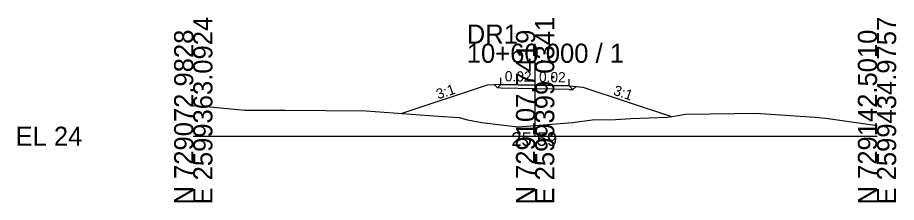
# Model space of a CAD drawing. Extents: x -26 to 1162, y -10 to 9515.
# Drawn here: x -25.7 to 102.8, y 2990.3 to 3017.4 of the extents above; entities that cross this region are included whole.
import ezdxf

# ---------------------------------------------------------------- set-up
doc = ezdxf.new("R2010")
doc.units = 0
for name, color, linetype in [('Exist Cross Section Cell', 7, 'Continuous'), ('Exist XS Center Line Elevation Label', 7, 'Continuous'), ('Exist XS Ground Line', 7, 'Continuous'), ('Prop XS Ditch Slope Text', 7, 'Continuous'), ('Prop XS Dump Level', 7, 'Continuous'), ('Prop XS EOT Tick Mark', 7, 'Continuous'), ('Prop XS Finish Grade', 7, 'Continuous'), ('Prop XS Finish Grade Earthwork', 7, 'Continuous'), ('Prop XS Finish Grade Pavement', 7, 'Continuous'), ('Prop XS Pvmt Edge Slope', 7, 'Continuous'), ('Prop XS SE Text', 7, 'Continuous'), ('Prop XS Subgrade Earthwork', 7, 'Continuous')]:
    doc.layers.add(name, color=color, linetype=linetype)

msp = doc.modelspace()

# ---------------------------------------------------------------- linework, layer by layer
at = {"layer": 'Exist Cross Section Cell'}
for p, q in [((50, 3000), (50, 3013.55)), ((0, 3000), (50, 3000)), ((50, 3000), (100, 3000))]:
    msp.add_line(p, q, dxfattribs=at)
at = {"layer": 'Exist XS Ground Line'}
msp.add_lwpolyline([(0, 3004.52), (0.89, 3004.45), (7.54, 3003.8), (13.39, 3003.84), (25.31, 3003.72), (35.83, 3002.93), (38.89, 3002.76), (40.1, 3002.4), (42.2, 3002.02), (44.6, 3001.74), (47.45, 3001.39), (50, 3001.59), (55.45, 3002), (58.36, 3002.42), (61.73, 3002.45), (64, 3002.59), (69.36, 3002.79), (70.62, 3003.01), (72.01, 3003.21), (79.15, 3003.35), (82.23, 3003.4), (90.94, 3002.77), (92.53, 3002.65), (100, 3001.56)], dxfattribs=at)
at = {"layer": 'Prop XS Dump Level'}
for p, q in [((50, 3007.46), (45, 3007.56)), ((45, 3007.56), (50, 3007.46)), ((55, 3007.36), (50, 3007.46)), ((50, 3007.46), (55, 3007.36))]:
    msp.add_line(p, q, dxfattribs=at)
at = {"layer": 'Prop XS EOT Tick Mark'}
for p, q in [((45, 3007.56), (45, 3008.56)), ((55, 3007.36), (55, 3008.36))]:
    msp.add_line(p, q, dxfattribs=at)
at = {"layer": 'Prop XS Finish Grade'}
for p, q in [((45, 3007.56), (44.06, 3007.53)), ((55, 3007.36), (55.98, 3007.29))]:
    msp.add_line(p, q, dxfattribs=at)
at = {"layer": 'Prop XS Finish Grade Earthwork'}
for p, q in [((43, 3007.48), (30.52, 3003.33)), ((44.06, 3007.53), (43, 3007.48)), ((55.98, 3007.29), (57, 3007.2)), ((57, 3007.2), (69.95, 3002.89))]:
    msp.add_line(p, q, dxfattribs=at)
at = {"layer": 'Prop XS Finish Grade Pavement'}
for p, q in [((45, 3007.56), (50, 3007.46)), ((50, 3007.46), (55, 3007.36))]:
    msp.add_line(p, q, dxfattribs=at)
at = {"layer": 'Prop XS Pvmt Edge Slope'}
for p, q in [((44.06, 3007.53), (44.51, 3007.07)), ((45, 3007.56), (44.51, 3007.07)), ((55, 3007.36), (55.51, 3006.85)), ((55.98, 3007.29), (55.51, 3006.85))]:
    msp.add_line(p, q, dxfattribs=at)
at = {"layer": 'Prop XS Subgrade Earthwork'}
for p, q in [((44.51, 3007.07), (44.06, 3007.53)), ((44.51, 3007.07), (44.06, 3007.53)), ((45, 3007.06), (44.51, 3007.07)), ((50, 3006.96), (45, 3007.06)), ((55, 3006.86), (50, 3006.96)), ((55, 3006.86), (55.51, 3006.85)), ((55.51, 3006.85), (55.98, 3007.29)), ((55.51, 3006.85), (55.98, 3007.29))]:
    msp.add_line(p, q, dxfattribs=at)

# ---------------------------------------------------------------- texts
at = {"layer": 'Exist Cross Section Cell'}
for s, p in [('E 2599363.0924', (2.8, 2990)), ('E 2599399.0341', (52.8, 2990)), ('E 2599434.9757', (102.8, 2990)), ('N 729072.9828', (0, 2990)), ('N 729107.7419', (50, 2990)), ('N 729142.5010', (100, 2990))]:
    msp.add_text(s, height=2.8, rotation=90, dxfattribs=at).set_placement(p)
for s, p in [('DR1', (40, 3013.55)), ('10+60.000 / 1', (40, 3010.75)), ('EL 24', (-26, 2998.6))]:
    msp.add_text(s, height=2.8, dxfattribs=at).set_placement(p)
at = {"layer": 'Exist XS Center Line Elevation Label'}
msp.add_text('25.59', height=2, dxfattribs=at).set_placement((46.52, 2998.59))
at = {"layer": 'Prop XS Ditch Slope Text'}
for rotation, p in [(18.4349, (35.82, 3005.39)), (341.5883, (61.33, 3006.09))]:
    msp.add_text('3:1', height=1.5, rotation=rotation, dxfattribs=at).set_placement(p)
at = {"layer": 'Prop XS Dump Level'}
for p in [(43, 3007.44), (57, 3007.16)]:
    msp.add_text('Case1', height=0.04, dxfattribs=at).set_placement(p)
at = {"layer": 'Prop XS SE Text'}
for p in [(45.55, 3008.05), (50.55, 3007.95)]:
    msp.add_text('0.02', height=1.5, rotation=358.8542, dxfattribs=at).set_placement(p)

doc.saveas('drawing.dxf')
